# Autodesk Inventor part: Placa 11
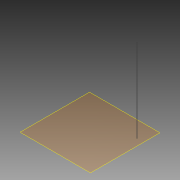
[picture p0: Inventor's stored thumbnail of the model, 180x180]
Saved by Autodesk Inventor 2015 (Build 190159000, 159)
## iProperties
Created: 2015-04
Part Number: Placa 11
Material: Generic
Document SubType Name: Modeling
Designer: suporte
Density: 1 g/cm^3
Appearance: Default
Author: suporte
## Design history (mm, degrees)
workplane "Work Plane1"
sketch "Sketch1"
  geometry: L1 (530.862, 800)-(812.5, 518.558) reference; L2 (530.862, 800)-(600.783, 869.97) reference; L3 (539.701, 808.839)-(575.057, 773.483) reference; L4 (539.701, 808.839)-(821.336, 527.4); L5 (882.421, 588.528)-(812.5, 518.558) reference; L6 (539.701, 808.839)-(821.336, 527.4); L7 (821.336, 527.4)-(812.5, 518.558); L8 (812.5, 518.558)-(530.862, 800); L9 (530.862, 800)-(539.701, 808.839); 1 further point
  constraints: 10 end point, 2 parallel, 2 perpendicular, 1 point on line
  dimensions: "d0" = 12.5 distance of L1.start L3.start (derived)
extrude "Extrusion1" new body sketch "Sketch1" distance "d1" = 2100; taper "d2" = 0 deg
body "Solid1"
node "Reference1"
node "Reference2"
node "Reference3"
node "Reference4"
